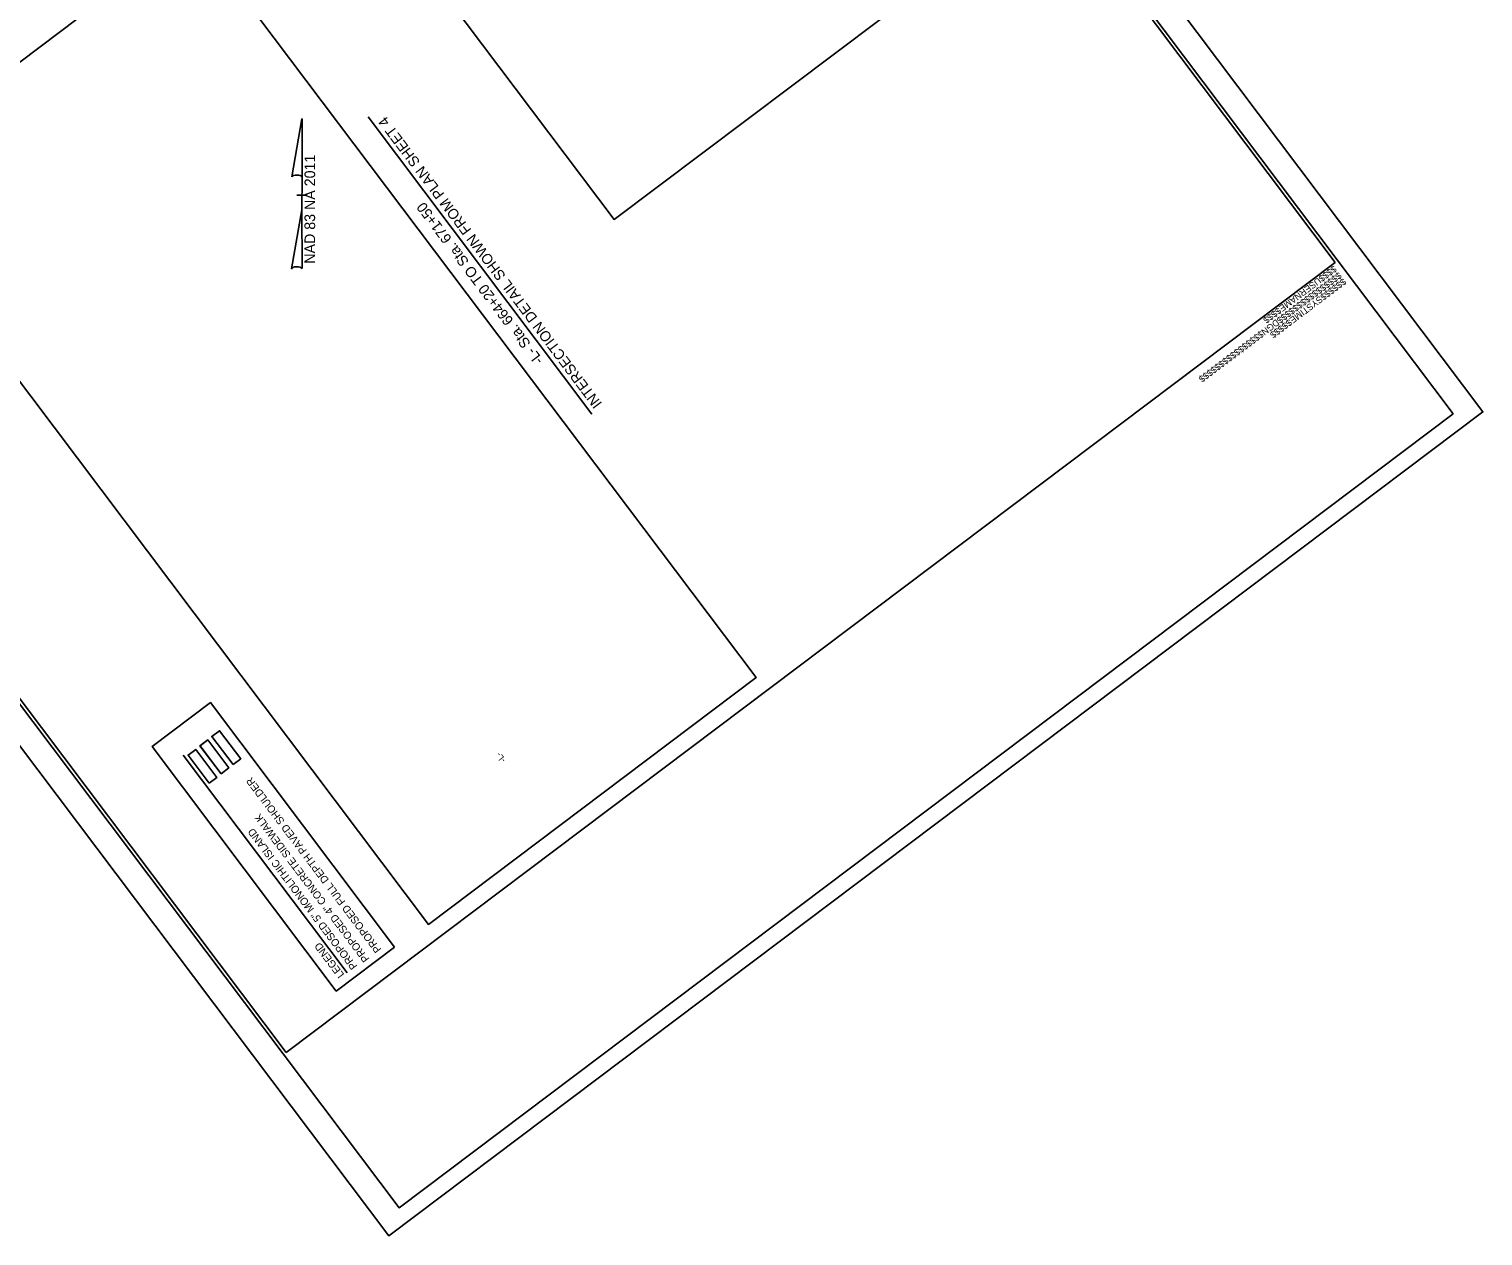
# Model space of a CAD drawing. Extents: x 1262861 to 1264804, y 775326 to 777329.
# Drawn here: x 1263642 to 1264804, y 775326 to 776290 of the extents above; entities that cross this region are included whole.
import ezdxf

# ---------------------------------------------------------------- set-up
doc = ezdxf.new("R2010")
doc.units = 0
for name, color, linetype in [('Old_Level_1', 7, 'Continuous'), ('Prop Dimension', 7, 'Continuous'), ('Prop Dimension Text', 7, 'Continuous'), ('Prop EOT', 7, 'Continuous'), ('Prop Horizontal Alignment Curve and Spiral Data', 7, 'Continuous'), ('Prop Shade Heavy', 7, 'Continuous'), ('Prop Shade Light', 7, 'Continuous'), ('Prop Shade Medium', 7, 'Continuous'), ('Sheet Plan CELL', 7, 'Continuous'), ('Sheet Plot Border Inside CELL', 7, 'Continuous'), ('Sheet Plot Border Outside CELL', 7, 'Continuous'), ('Sheet Typical CELL', 7, 'Continuous')]:
    doc.layers.add(name, color=color, linetype=linetype)

msp = doc.modelspace()

# ---------------------------------------------------------------- linework, layer by layer
at = {"layer": 'Old_Level_1'}
for p, q in [((1263851.7, 776172.3), (1263859.9, 776218.6)), ((1263860, 776218.6), (1263859.9, 776218.6)), ((1263860, 776218.6), (1263859.9, 776218.6)), ((1263860, 776218.6), (1263860, 776170.8)), ((1263859.9, 776146), (1263860, 776172.2)), ((1263860, 776170.8), (1263860, 776172.2)), ((1263859.5, 776157.6), (1263855.9, 776157.6)), ((1263855.9, 776157.6), (1263855.9, 776157.6)), ((1263856, 776157.6), (1263864, 776157.6)), ((1263859.9, 776146), (1263851.6, 776098.8)), ((1263860, 776099), (1263859.9, 776146))]:
    msp.add_line(p, q, dxfattribs=at)
for centre, start_param, end_param in [((1263855.8, 776171.8), 0.216388, 2.908219), ((1263855.8, 776098.6), 0.201328, 3.141593)]:
    msp.add_ellipse(centre, major_axis=(4.23, -0.03), ratio=0.461098, start_param=start_param, end_param=end_param, dxfattribs=at)
at = {"layer": 'Prop Dimension'}
msp.add_line((1263895.9, 775536.1), (1263765, 775710.1), dxfattribs=at)
at = {"layer": 'Prop EOT'}
for points in [[(1263804.8, 775702.6), (1263787.9, 775725), (1263794, 775729.6), (1263810.9, 775707.2)], [(1263785.8, 775687.7), (1263768.9, 775710.1), (1263775, 775714.7), (1263791.9, 775692.3)], [(1263795.3, 775695.2), (1263778.4, 775717.6), (1263784.5, 775722.2), (1263801.4, 775699.8)]]:
    msp.add_lwpolyline(points, close=True, dxfattribs=at)
at = {"layer": 'Prop Horizontal Alignment Curve and Spiral Data'}
msp.add_line((1264091.6, 775982.7), (1263912.7, 776220.2), dxfattribs=at)
at = {"layer": 'Prop Shade Heavy'}
for p, q in [((1263775, 775714.7), (1263791.9, 775692.3)), ((1263785.8, 775687.7), (1263768.9, 775710.1)), ((1263791.9, 775692.3), (1263785.8, 775687.7)), ((1263785.8, 775687.7), (1263785.8, 775687.7))]:
    msp.add_line(p, q, dxfattribs=at)
msp.add_ellipse((1263775, 775714.7), major_axis=(-0.000000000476, -0.000000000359), ratio=0.894427, start_param=3.141593, end_param=3.521844, dxfattribs=at)
at = {"layer": 'Prop Shade Light'}
for p, q in [((1263794, 775729.6), (1263787.8, 775725)), ((1263787.8, 775725), (1263804.8, 775702.6)), ((1263804.8, 775702.6), (1263810.9, 775707.2))]:
    msp.add_line(p, q, dxfattribs=at)
msp.add_lwpolyline([(1263810.9, 775707.2), (1263794, 775729.6)], dxfattribs=at)
msp.add_ellipse((1263787.8, 775725), major_axis=(-0.018, -0.0081), ratio=0.299083, start_param=5.584494, end_param=6.511789, dxfattribs=at)
at = {"layer": 'Prop Shade Medium'}
for p, q in [((1263784.5, 775722.2), (1263778.3, 775717.5)), ((1263778.3, 775717.5), (1263795.3, 775695.2)), ((1263795.3, 775695.2), (1263801.4, 775699.8))]:
    msp.add_line(p, q, dxfattribs=at)
msp.add_lwpolyline([(1263801.4, 775699.8), (1263784.5, 775722.2)], dxfattribs=at)
msp.add_ellipse((1263778.3, 775717.5), major_axis=(-0.018, -0.0081), ratio=0.299083, start_param=5.584494, end_param=6.511789, dxfattribs=at)
at = {"layer": 'Sheet Plot Border Inside CELL'}
msp.add_lwpolyline([(1264780.2, 775982.9), (1263777.9, 777313.6), (1262935.2, 776678.9), (1263937.5, 775348.2)], close=True, dxfattribs=at)
at = {"layer": 'Sheet Plot Border Outside CELL'}
msp.add_lwpolyline([(1262916.5, 776670.5), (1263929.4, 775325.7), (1264804, 775984.5), (1263791.2, 777329.3)], close=True, dxfattribs=at)
at = {"layer": 'Sheet Typical CELL'}
for p, q in [((1263783.4, 777302.1), (1264685.9, 776104)), ((1263847.2, 775472.3), (1262944.7, 776670.4)), ((1264685.9, 776104), (1263847.2, 775472.3))]:
    msp.add_line(p, q, dxfattribs=at)
for points in [[(1264392.9, 776351.8), (1263932.9, 776962.7), (1263649.3, 776749.1), (1264109.4, 776138.3)], [(1263511.4, 776171.6), (1263961, 775574.7), (1264222.9, 775772), (1263773.3, 776368.9)], [(1263933.9, 775556.5), (1263786.7, 775752.1), (1263740, 775716.9), (1263887.3, 775521.4)]]:
    msp.add_lwpolyline(points, close=True, dxfattribs=at)

# ---------------------------------------------------------------- texts
at = {"layer": 'Old_Level_1'}
msp.add_text('NAD 83 NA 2011', height=8.5, rotation=89.9761, dxfattribs=at).set_placement((1263870.4, 776102.9))
at = {"layer": 'Prop Dimension'}
msp.add_text('-L-', height=5, rotation=126.9874, dxfattribs=at).set_placement((1264023.1, 775706.3))
at = {"layer": 'Prop Dimension Text'}
for s, p in [('PROPOSED FULL DEPTH PAVED SHOULDER ', (1263923.6, 775554.8)), ('PROPOSED 4" CONCRETE SIDEWALK', (1263914.1, 775547.3)), ('PROPOSED 5" MONOLITHIC ISLAND', (1263904.4, 775541.4)), ('LEGEND', (1263894, 775534.6))]:
    msp.add_text(s, height=6, rotation=126.9877, dxfattribs=at).set_placement(p)
at = {"layer": 'Prop Horizontal Alignment Curve and Spiral Data'}
for s, p in [('INTERSECTION DETAIL SHOWN FROM PLAN SHEET 4', (1264100.2, 775991.2)), ('-L- Sta. 664+20 TO Sta. 671+50', (1264053.2, 776025.9))]:
    msp.add_text(s, height=8.32, rotation=126.9874, dxfattribs=at).set_placement(p)
at = {"layer": 'Sheet Plan CELL'}
for s, p in [('$$$$$$$$$$$$$$$$DGN$$$$$$$$$$$$$$$$', (1264688.6, 776096.5)), ('$$$$USERNAME$$$$', (1264684.6, 776101.7)), ('$$$$$$SYSTIME$$$$$', (1264692.2, 776091.6))]:
    msp.add_text(s, height=5.25, rotation=216.9874, dxfattribs=at).set_placement(p)

doc.saveas('drawing.dxf')
